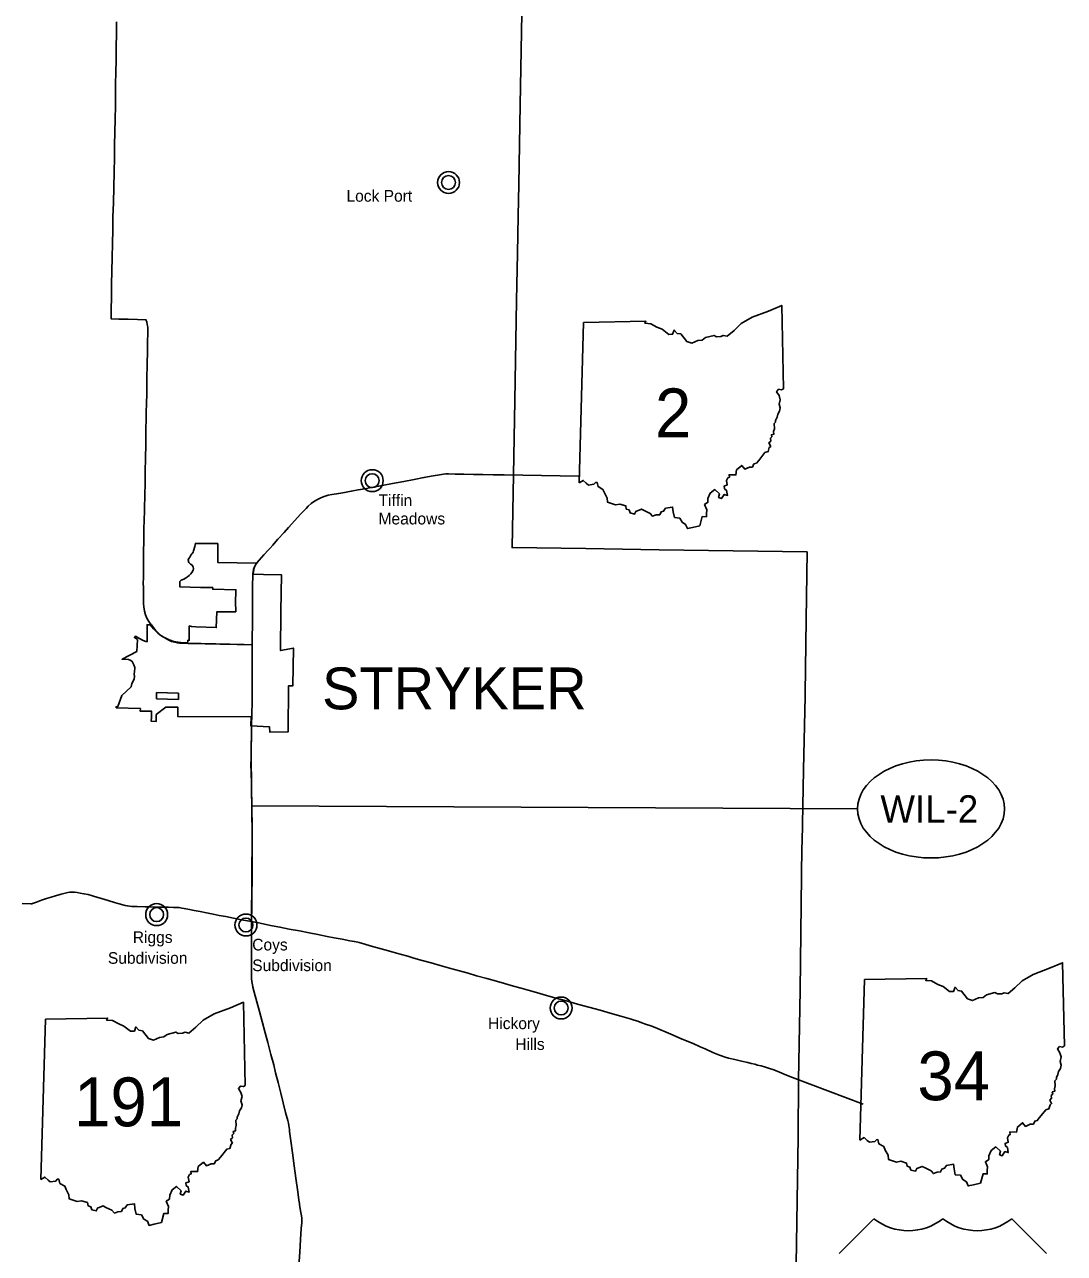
# Model space of a CAD drawing. Extents: x -66 to 795, y 0 to 440.
# Drawn here: x 443.5 to 549.7, y 93.6 to 219 of the extents above; entities that cross this region are included whole.
import ezdxf

# ---------------------------------------------------------------- set-up
doc = ezdxf.new("R2010")
doc.units = 0
for name, color, linetype in [('DV_X_Corp_Line', 7, 'Continuous'), ('GM_X_Corporation_Text', 7, 'Continuous'), ('GM_X_County', 7, 'Continuous'), ('GM_X_State_Route', 7, 'Continuous'), ('PV_P_Text', 7, 'Continuous'), ('RD_P_Fence', 7, 'Continuous'), ('SH_Data', 7, 'Continuous')]:
    doc.layers.add(name, color=color, linetype=linetype)

msp = doc.modelspace()

# ---------------------------------------------------------------- linework, layer by layer
at = {"layer": 'DV_X_Corp_Line'}
for points in [[(452.87, 149.31), (452.87, 149.41), (453.03, 149.42), (453.46, 150.54), (454.41, 151.44), (454.47, 151.77), (454.7, 152.23), (454.73, 152.52), (454.71, 152.71), (454.75, 153.03), (454.78, 153.31), (454.77, 153.42), (454.69, 153.67), (454.51, 154.03), (454.47, 154.07), (454.3, 154.16), (454.12, 154.23), (453.77, 154.26), (453.58, 154.26), (453.47, 154.26), (455, 155.05), (455.06, 156.26), (454.73, 156.47), (454.85, 156.62), (455.18, 156.42), (455.64, 156.15), (455.89, 156.05), (456.03, 156.03), (456.03, 157.77), (456.36, 157.77), (456.55, 157.51), (456.68, 157.36), (456.85, 157.18), (456.98, 157.05), (457.13, 156.92), (457.3, 156.78), (457.45, 156.67), (457.65, 156.55), (457.8, 156.46), (458.2, 156.27), (458.39, 156.19), (458.77, 156.08), (458.98, 156.03), (459.21, 155.99), (459.48, 155.96), (460.16, 155.93), (460.19, 156.07), (460.2, 156.19), (460.34, 156.19), (460.34, 157.65), (460.55, 157.61), (461, 157.57), (463.09, 157.48), (463.14, 159.08), (465.08, 159.1), (465.08, 159.6), (465.07, 159.64), (465.06, 159.93), (465.09, 161.35), (462.73, 161.4), (462.73, 161.57), (461.47, 161.59), (459.38, 161.63), (459.36, 162.18), (459.5, 162.31), (459.79, 162.43), (459.96, 162.53), (460.17, 162.67), (460.31, 162.81), (460.49, 162.97), (460.59, 163.1), (460.73, 163.34), (460.76, 163.51), (460.75, 163.64), (460.74, 163.7), (460.59, 163.89), (460.47, 163.95), (460.37, 164.05), (460.29, 164.13), (460.22, 164.35), (460.25, 164.45), (460.26, 164.52), (460.28, 164.55), (460.38, 164.66), (460.44, 164.75), (460.5, 164.88), (460.6, 165), (460.68, 165.08), (460.73, 165.19), (460.76, 165.32), (460.89, 165.76), (460.96, 166.08), (463.25, 166.05), (463.25, 164.13), (467.19, 164.05), (467.09, 163.88), (466.96, 163.58), (466.89, 163.22), (466.86, 162.93), (467.92, 162.89), (469.74, 162.87), (469.68, 159.11), (469.65, 155.14), (470.96, 155.39), (470.92, 151.54), (470.48, 151.54), (470.42, 146.83), (468.55, 146.82), (468.54, 147.34), (466.63, 147.44), (466.66, 148.37), (459.16, 148.42), (459.17, 148.73), (459.17, 149.36), (457.96, 149.37), (456.97, 148.61), (456.96, 147.9), (456.45, 147.92), (456.47, 148.29), (456.48, 148.96), (455.34, 148.95), (455.35, 149.21)], [(456.99, 150.21), (459.22, 150.15), (459.23, 150.79), (457, 150.85)]]:
    msp.add_lwpolyline(points, close=True, dxfattribs=at)
for centre, radius in [((486.8, 202.91), 1.12), ((486.8, 202.91), 0.71), ((479.01, 172.48), 1.12), ((479.01, 172.48), 0.71), ((457.01, 128.19), 1.12), ((457.01, 128.19), 0.71), ((466.12, 127.13), 1.12), ((466.12, 127.13), 0.71), ((498.29, 118.66), 1.12), ((498.29, 118.66), 0.71)]:
    msp.add_circle(centre, radius, dxfattribs=at)
at = {"layer": 'GM_X_County'}
msp.add_lwpolyline([(522.24, 90.34), (522.47, 105.46), (522.51, 111.32), (522.67, 120.49), (522.87, 135.08), (522.88, 135.57), (523.03, 142.97), (523.18, 150.5), (523.18, 150.8), (523.29, 158.31), (523.39, 165.21), (508.31, 165.43), (500.82, 165.54), (493.28, 165.65), (493.42, 173.06), (493.56, 180.62), (493.75, 190.86), (493.84, 195.67), (493.91, 199.51), (493.97, 202.71), (494.12, 210.82), (494.26, 218.28), (494.39, 225.79)], dxfattribs=at)
at = {"layer": 'GM_X_State_Route'}
for points in [[(452.36, 189.87), (452.36, 190), (452.39, 191.13), (452.41, 192.49), (452.44, 193.89), (452.46, 195.21), (452.5, 196.72), (452.52, 198.03), (452.55, 199.39), (452.59, 200.85), (452.67, 203.99), (452.7, 205.41), (452.72, 206.73), (452.74, 208.05), (452.77, 209.37), (452.79, 210.72), (452.8, 211.88), (452.82, 212.98), (452.84, 214.13), (452.87, 215.39), (452.89, 216.71), (452.9, 218.12), (452.92, 219.3)], [(456.45, 157.78), (456.45, 157.78), (456.21, 158.11), (456.01, 158.46), (455.88, 158.77), (455.78, 159.17), (455.71, 159.59), (455.68, 159.94), (455.66, 160.44), (455.66, 161.24), (455.65, 161.61), (455.64, 161.97), (455.66, 162.59), (455.65, 163.58), (455.66, 164.44), (455.67, 165.34), (455.69, 166.2), (455.69, 166.31), (455.7, 167.37), (455.74, 168.64), (455.75, 169.18), (455.76, 169.69), (455.79, 170.94), (455.83, 172.29), (455.84, 173.41), (455.88, 174.79), (455.9, 176.16), (455.91, 177.72), (455.94, 178.76), (455.95, 179.45), (455.98, 180.4), (455.99, 181.31), (456, 181.51), (456.01, 182.93), (456.04, 184.3), (456.06, 185.77), (456.08, 186.74), (456.11, 187.44), (456.12, 187.85), (456.09, 188.16), (456.05, 188.42), (455.99, 188.68), (455.94, 188.84), (455.92, 188.9), (455.04, 188.93), (454.11, 188.95), (453.13, 188.97), (452.36, 189), (452.36, 189.87), (452.36, 189.87)], [(468.55, 165.56), (468.85, 165.89), (469.01, 166.08), (469.39, 166.5), (470.01, 167.18), (470.48, 167.71), (471.12, 168.42), (471.69, 169.06), (472.25, 169.65), (472.47, 169.89), (472.78, 170.15), (473, 170.31), (473.37, 170.53), (473.68, 170.69), (473.99, 170.84), (474.22, 170.9), (474.51, 170.99), (474.9, 171.05), (475.6, 171.17), (476.17, 171.26), (476.86, 171.39), (477.58, 171.53), (478.27, 171.66), (478.9, 171.78), (478.96, 171.79), (480.02, 171.99), (481.08, 172.2), (482.24, 172.41), (483.29, 172.61), (484.28, 172.79), (485.22, 172.97), (485.88, 173.09), (486.07, 173.12), (486.29, 173.15), (486.51, 173.16), (486.79, 173.16), (487.48, 173.15), (488.37, 173.13), (489.33, 173.12), (489.56, 173.11), (490.31, 173.1), (491.35, 173.09), (492.48, 173.08), (500.09, 172.95)], [(466.82, 162.73), (466.82, 162.8), (466.82, 162.96), (466.85, 163.22), (466.9, 163.42), (466.97, 163.63), (467.09, 163.88), (467.26, 164.12), (467.47, 164.38), (467.93, 164.9), (468.41, 165.41), (468.55, 165.56)], [(466.78, 157.97), (466.78, 158.25), (466.78, 158.5), (466.78, 159.02), (466.79, 159.49), (466.79, 159.57), (466.79, 160.57), (466.79, 161.38), (466.8, 161.98), (466.81, 162.56), (466.82, 162.73), (466.82, 162.73)], [(457.58, 156.61), (457.57, 156.61), (457.45, 156.69), (457.05, 157.04), (456.78, 157.37), (456.48, 157.75), (456.45, 157.78)], [(466.77, 156.63), (466.78, 157.64), (466.78, 157.97)], [(458.08, 156.3), (457.77, 156.47), (457.67, 156.54), (457.58, 156.61)], [(460.23, 155.87), (459.69, 155.88), (459.34, 155.88), (459.13, 155.92), (458.86, 155.98), (458.53, 156.08), (458.19, 156.23), (458.08, 156.3)], [(463.06, 155.81), (463.05, 155.81), (463.04, 155.82), (462.55, 155.83), (461.96, 155.84), (461.56, 155.85), (460.59, 155.87), (460.24, 155.87), (460.23, 155.87)], [(466.77, 155.73), (465.94, 155.76), (465.23, 155.76), (465.21, 155.76), (464.48, 155.78), (464.29, 155.79), (463.46, 155.8), (463.06, 155.81)], [(466.77, 155.73), (466.77, 156.59), (466.77, 156.61), (466.77, 156.62), (466.77, 156.63)], [(466.77, 154.09), (466.77, 154.09), (466.77, 154.85), (466.77, 154.96), (466.77, 155.73)], [(466.77, 151.55), (466.77, 151.55), (466.77, 151.6), (466.77, 151.66), (466.76, 152.26), (466.76, 152.53), (466.76, 153.09), (466.76, 153.23), (466.77, 154.04), (466.77, 154.09)], [(466.71, 148.41), (466.71, 148.41), (466.72, 148.66), (466.72, 148.76), (466.75, 149.85), (466.75, 149.93), (466.76, 150.6), (466.77, 150.9), (466.77, 151.19), (466.77, 151.55)], [(466.7, 147.51), (466.7, 147.52), (466.7, 147.76), (466.71, 148.41)], [(466.7, 127.48), (466.71, 129.07), (466.73, 130.34), (466.74, 131.75), (466.75, 133.12), (466.76, 134.32), (466.77, 135.55), (466.77, 136.31), (466.76, 136.78), (466.74, 137.66), (466.73, 138.61), (466.72, 139.5), (466.7, 140.56), (466.67, 141.56), (466.66, 142.67), (466.63, 143.54), (466.64, 144.08), (466.66, 145.26), (466.7, 146.66), (466.7, 147.51)], [(443.29, 129.31), (444.17, 129.3), (444.28, 129.3), (444.33, 129.31), (444.45, 129.35), (444.75, 129.46), (445.27, 129.66), (445.76, 129.82), (446.23, 129.98), (446.69, 130.11), (447.27, 130.28), (447.67, 130.38), (447.95, 130.44), (448.14, 130.47), (448.38, 130.48), (448.61, 130.47), (448.91, 130.44), (449.2, 130.39), (449.59, 130.32), (450, 130.23), (450.45, 130.11), (451.01, 129.94), (451.63, 129.76), (452.15, 129.6), (452.71, 129.43), (453.19, 129.29), (453.54, 129.2), (453.8, 129.12), (454.02, 129.07), (454.22, 129.05), (454.48, 129.02), (454.72, 129.01), (455.02, 129), (455.83, 128.98), (456.14, 128.97), (456.77, 128.95), (457.56, 128.95), (457.91, 128.95), (458.23, 128.94), (458.74, 128.93), (459.09, 128.91), (459.31, 128.91), (459.56, 128.86), (459.83, 128.81), (460.36, 128.71), (460.85, 128.61), (461.46, 128.49), (462.11, 128.36), (462.79, 128.23), (463.38, 128.11), (464.07, 127.98), (464.84, 127.84), (465.67, 127.67), (466.7, 127.48)], [(471.53, 92.35), (471.63, 93.75), (471.7, 95.03), (471.76, 96.14), (471.81, 96.74), (471.82, 97.04), (471.82, 97.22), (471.79, 97.43), (471.7, 97.96), (471.58, 98.59), (471.57, 98.69), (471.53, 99.05), (471.4, 99.91), (471.22, 101.28), (471.05, 102.54), (470.87, 103.87), (470.7, 105.09), (470.57, 106.06), (470.55, 106.26), (470.5, 106.66), (470.45, 106.9), (470.38, 107.19), (470.16, 108), (469.91, 108.99), (469.67, 109.97), (469.4, 111.04), (469.15, 112.05), (468.96, 112.85), (468.66, 113.91), (468.34, 115.14), (468.08, 116.12), (467.77, 117.27), (467.5, 118.3), (467.24, 119.28), (466.96, 120.28), (466.84, 120.77), (466.79, 121.03), (466.72, 121.35), (466.69, 121.66), (466.67, 122), (466.67, 122.66), (466.67, 123.49), (466.68, 124.39), (466.69, 125.37), (466.7, 127.48)], [(466.7, 127.48), (467.58, 127.31), (468.63, 127.09), (469.59, 126.91), (470.52, 126.72), (471.57, 126.53), (472.56, 126.33), (473.45, 126.16), (474.42, 125.97), (475.14, 125.83), (475.94, 125.68), (476.73, 125.52), (477.19, 125.43), (477.53, 125.37), (477.67, 125.34), (478.27, 125.17), (478.81, 125.01), (479.55, 124.8), (480.31, 124.6), (481.14, 124.36), (481.86, 124.16), (482.63, 123.94), (483.27, 123.76), (484.12, 123.52), (485.04, 123.27), (485.95, 123.01), (486.88, 122.74), (487.91, 122.46), (488.81, 122.21), (489.64, 121.95), (490.69, 121.67)], [(490.69, 121.67), (490.69, 121.67), (491.68, 121.39), (492.51, 121.16), (493.44, 120.9), (494.21, 120.68), (494.92, 120.49), (495.79, 120.24), (496.79, 119.93), (497.02, 119.86), (497.63, 119.69), (498.93, 119.34), (499.97, 119.05), (501.13, 118.73), (502.26, 118.42), (503.28, 118.12), (504.37, 117.82), (505.32, 117.54), (505.75, 117.43), (506.11, 117.3), (506.51, 117.16), (506.9, 117.02), (507.44, 116.83), (507.89, 116.66), (508.36, 116.45), (509, 116.19), (509.74, 115.87), (510.42, 115.58), (511.16, 115.26), (511.75, 115.04), (512.47, 114.71), (512.98, 114.48), (513.77, 114.11), (514.44, 113.84), (514.66, 113.76), (515.03, 113.64), (515.38, 113.53), (516, 113.39), (516.7, 113.22), (517.33, 113.08), (517.69, 113.01), (518.06, 112.91), (518.34, 112.84), (518.72, 112.75), (519.16, 112.62), (519.57, 112.5), (519.88, 112.38), (520.16, 112.28), (520.58, 112.11), (521.3, 111.8), (521.89, 111.56), (529.1, 108.83)]]:
    msp.add_lwpolyline(points, dxfattribs=at)
at = {"layer": 'PV_P_Text'}
for p, q in [((500.12, 172.26), (500.58, 188.63)), ((528.79, 105.18), (529.25, 121.56)), ((528.79, 105.18), (529.25, 121.56)), ((445.19, 101.15), (445.65, 117.52)), ((530.2, 97.15), (526.66, 93.61)), ((530.2, 97.15), (526.66, 93.61)), ((547.84, 93.61), (544.3, 97.15)), ((547.84, 93.61), (544.3, 97.15))]:
    msp.add_line(p, q, dxfattribs=at)
for points in [[(500.58, 188.63), (506.94, 188.74), (506.84, 188.54), (507.44, 188.5), (508.07, 188.15), (508.61, 187.93), (509.27, 187.41), (509.66, 187.42), (509.83, 187.84), (510.13, 187.51), (510.49, 187.45), (511.11, 186.67), (511.62, 186.5), (512.23, 186.77), (512.69, 186.81), (513.03, 187.08), (513.9, 187.31), (514.14, 187.17), (514.6, 187.2), (514.83, 187.3), (515.24, 187.21), (515.95, 187.8), (516.67, 188.51), (517.8, 189.17), (519.47, 189.79), (520.8, 190.36), (520.99, 181.86)], [(520.99, 181.86), (520.79, 181.74), (520.49, 181.8), (520.28, 181.56), (520.54, 181.16), (520.66, 180.74), (520.55, 180.28), (520.66, 179.9), (520.58, 179.58), (520.39, 179.26), (520.33, 178.95), (520.16, 178.63), (520.18, 178.46), (520.02, 178.31), (520.05, 177.78), (519.97, 177.49), (520, 177.23), (519.75, 177.17), (519.81, 176.96), (519.65, 176.8), (519.68, 176.52), (519.5, 176.34), (519.68, 175.98), (519.53, 175.87), (519.42, 175.44), (519.09, 175.35), (518.45, 174.55), (518.22, 174.26), (517.96, 174.18), (517.82, 173.87), (517.51, 173.87), (517.03, 173.66), (516.72, 174.03), (516.18, 173.58), (516.12, 173.07), (515.43, 173.09), (515.46, 172.83), (515.31, 172.76), (515.17, 172.5), (515.25, 172.04), (514.93, 171.92), (514.97, 171.65), (515.17, 171.49), (515.27, 170.98), (514.93, 171.08), (514.65, 170.65), (514.36, 170.75), (514.45, 171.12), (513.97, 171.56), (513.51, 171.21), (513.27, 170.65), (513.27, 170.27), (512.93, 170.04), (513.15, 169.51), (513.11, 169.14), (513.12, 168.79), (512.69, 168.81), (512.43, 167.87)], [(512.43, 167.87), (511.69, 167.69), (511.17, 167.58), (510.99, 168.01), (510.63, 168.23), (510.39, 168.66), (509.86, 168.72), (509.73, 169.31), (509.67, 169.79), (508.95, 169.67), (508.75, 169.38), (508.5, 169.3), (508.35, 169), (508, 168.98), (507.62, 168.84), (507.38, 169.13), (506.76, 169.42), (506.49, 169.57), (505.91, 169.34), (505.79, 169.06), (505.33, 169.18), (505.22, 169.49), (504.94, 169.58), (504.88, 169.91), (504.29, 170.08), (503.83, 170.01), (503.03, 170.28), (502.98, 170.7), (502.71, 171.23), (502.56, 171.59), (502.06, 171.87), (501.95, 172.3), (501.79, 172.29), (501.64, 172.11), (501.08, 172.03), (500.86, 172.21), (500.54, 172.51), (500.12, 172.26)], [(529.25, 121.56), (535.6, 121.66), (535.5, 121.47), (536.1, 121.42), (536.74, 121.07), (537.28, 120.85), (537.94, 120.33), (538.33, 120.34), (538.5, 120.77), (538.8, 120.44), (539.16, 120.38), (539.78, 119.59), (540.29, 119.42), (540.9, 119.69), (541.36, 119.74), (541.69, 120), (542.56, 120.23), (542.81, 120.09), (543.27, 120.12), (543.5, 120.22), (543.9, 120.13), (544.61, 120.73), (545.34, 121.43), (546.46, 122.09), (548.14, 122.72), (549.46, 123.28), (549.66, 114.78)], [(529.25, 121.56), (535.6, 121.66), (535.5, 121.47), (536.1, 121.42), (536.74, 121.07), (537.28, 120.85), (537.94, 120.33), (538.33, 120.34), (538.5, 120.77), (538.8, 120.44), (539.16, 120.38), (539.78, 119.59), (540.29, 119.42), (540.9, 119.69), (541.36, 119.74), (541.69, 120), (542.56, 120.23), (542.81, 120.09), (543.27, 120.12), (543.5, 120.22), (543.9, 120.13), (544.61, 120.73), (545.34, 121.43), (546.46, 122.09), (548.14, 122.72), (549.46, 123.28), (549.66, 114.78)], [(445.65, 117.52), (452, 117.63), (451.9, 117.43), (452.5, 117.39), (453.14, 117.04), (453.67, 116.82), (454.33, 116.3), (454.73, 116.31), (454.89, 116.73), (455.2, 116.4), (455.55, 116.34), (456.17, 115.56), (456.68, 115.39), (457.3, 115.66), (457.75, 115.7), (458.09, 115.97), (458.96, 116.2), (459.2, 116.06), (459.66, 116.09), (459.9, 116.19), (460.3, 116.1), (461.01, 116.69), (461.74, 117.4), (462.86, 118.06), (464.54, 118.69), (465.86, 119.25), (466.05, 110.75)], [(549.66, 114.78), (549.46, 114.66), (549.16, 114.72), (548.95, 114.48), (549.2, 114.08), (549.32, 113.66), (549.22, 113.2), (549.32, 112.82), (549.25, 112.5), (549.06, 112.18), (548.99, 111.88), (548.83, 111.56), (548.84, 111.38), (548.69, 111.24), (548.72, 110.71), (548.64, 110.41), (548.67, 110.16), (548.41, 110.09), (548.47, 109.88), (548.31, 109.72), (548.35, 109.44), (548.17, 109.26), (548.34, 108.91), (548.2, 108.79), (548.08, 108.36), (547.76, 108.27), (547.11, 107.48), (546.89, 107.18), (546.63, 107.1), (546.49, 106.8), (546.17, 106.8), (545.7, 106.58), (545.39, 106.95), (544.85, 106.51), (544.78, 106), (544.1, 106.01), (544.13, 105.75), (543.98, 105.68), (543.84, 105.42), (543.92, 104.96), (543.6, 104.84), (543.64, 104.58), (543.84, 104.41), (543.93, 103.9), (543.59, 104.01), (543.31, 103.58), (543.03, 103.68), (543.12, 104.04), (542.64, 104.48), (542.18, 104.13), (541.94, 103.57), (541.94, 103.19), (541.6, 102.97), (541.81, 102.43), (541.77, 102.07), (541.78, 101.72), (541.36, 101.73), (541.1, 100.79)], [(549.66, 114.78), (549.46, 114.66), (549.16, 114.72), (548.95, 114.48), (549.2, 114.08), (549.32, 113.66), (549.22, 113.2), (549.32, 112.82), (549.25, 112.5), (549.06, 112.18), (548.99, 111.88), (548.83, 111.56), (548.84, 111.38), (548.69, 111.24), (548.72, 110.71), (548.64, 110.41), (548.67, 110.16), (548.41, 110.09), (548.47, 109.88), (548.31, 109.72), (548.35, 109.44), (548.17, 109.26), (548.34, 108.91), (548.2, 108.79), (548.08, 108.36), (547.76, 108.27), (547.11, 107.48), (546.89, 107.18), (546.63, 107.1), (546.49, 106.8), (546.17, 106.8), (545.7, 106.58), (545.39, 106.95), (544.85, 106.51), (544.78, 106), (544.1, 106.01), (544.13, 105.75), (543.98, 105.68), (543.84, 105.42), (543.92, 104.96), (543.6, 104.84), (543.64, 104.58), (543.84, 104.41), (543.93, 103.9), (543.59, 104.01), (543.31, 103.58), (543.03, 103.68), (543.12, 104.04), (542.64, 104.48), (542.18, 104.13), (541.94, 103.57), (541.94, 103.19), (541.6, 102.97), (541.81, 102.43), (541.77, 102.07), (541.78, 101.72), (541.36, 101.73), (541.1, 100.79)], [(466.05, 110.75), (465.86, 110.63), (465.55, 110.69), (465.35, 110.45), (465.6, 110.05), (465.72, 109.63), (465.61, 109.17), (465.72, 108.79), (465.65, 108.47), (465.46, 108.15), (465.39, 107.85), (465.23, 107.53), (465.24, 107.35), (465.09, 107.21), (465.11, 106.67), (465.04, 106.38), (465.06, 106.13), (464.81, 106.06), (464.87, 105.85), (464.71, 105.69), (464.74, 105.41), (464.56, 105.23), (464.74, 104.87), (464.6, 104.76), (464.48, 104.33), (464.16, 104.24), (463.51, 103.45), (463.28, 103.15), (463.03, 103.07), (462.88, 102.76), (462.57, 102.76), (462.09, 102.55), (461.78, 102.92), (461.24, 102.47), (461.18, 101.96), (460.5, 101.98), (460.52, 101.72), (460.37, 101.65), (460.23, 101.39), (460.31, 100.93), (459.99, 100.81), (460.03, 100.54), (460.24, 100.38), (460.33, 99.87), (459.99, 99.97), (459.71, 99.55), (459.42, 99.65), (459.52, 100.01), (459.03, 100.45), (458.58, 100.1), (458.34, 99.54), (458.33, 99.16), (457.99, 98.93), (458.21, 98.4), (458.17, 98.03), (458.18, 97.68), (457.75, 97.7), (457.49, 96.76)], [(541.1, 100.79), (540.36, 100.61), (539.84, 100.5), (539.66, 100.93), (539.29, 101.15), (539.05, 101.58), (538.52, 101.64), (538.4, 102.23), (538.34, 102.71), (537.62, 102.59), (537.42, 102.3), (537.16, 102.22), (537.01, 101.93), (536.66, 101.9), (536.29, 101.76), (536.04, 102.05), (535.43, 102.34), (535.15, 102.49), (534.58, 102.26), (534.45, 101.99), (533.99, 102.11), (533.89, 102.41), (533.61, 102.51), (533.55, 102.83), (532.95, 103.01), (532.5, 102.94), (531.7, 103.2), (531.65, 103.63), (531.37, 104.15), (531.23, 104.52), (530.72, 104.79), (530.62, 105.22), (530.46, 105.21), (530.31, 105.04), (529.75, 104.96), (529.52, 105.13), (529.21, 105.43), (528.79, 105.18)], [(541.1, 100.79), (540.36, 100.61), (539.84, 100.5), (539.66, 100.93), (539.29, 101.15), (539.05, 101.58), (538.52, 101.64), (538.4, 102.23), (538.34, 102.71), (537.62, 102.59), (537.42, 102.3), (537.16, 102.22), (537.01, 101.93), (536.66, 101.9), (536.29, 101.76), (536.04, 102.05), (535.43, 102.34), (535.15, 102.49), (534.58, 102.26), (534.45, 101.99), (533.99, 102.11), (533.89, 102.41), (533.61, 102.51), (533.55, 102.83), (532.95, 103.01), (532.5, 102.94), (531.7, 103.2), (531.65, 103.63), (531.37, 104.15), (531.23, 104.52), (530.72, 104.79), (530.62, 105.22), (530.46, 105.21), (530.31, 105.04), (529.75, 104.96), (529.52, 105.13), (529.21, 105.43), (528.79, 105.18)], [(457.49, 96.76), (456.75, 96.58), (456.24, 96.47), (456.06, 96.9), (455.69, 97.12), (455.45, 97.55), (454.92, 97.61), (454.79, 98.2), (454.74, 98.68), (454.01, 98.56), (453.81, 98.27), (453.56, 98.19), (453.41, 97.89), (453.06, 97.87), (452.69, 97.73), (452.44, 98.02), (451.83, 98.31), (451.55, 98.46), (450.97, 98.23), (450.85, 97.95), (450.39, 98.07), (450.28, 98.38), (450, 98.47), (449.94, 98.8), (449.35, 98.97), (448.89, 98.9), (448.09, 99.17), (448.04, 99.6), (447.77, 100.12), (447.63, 100.48), (447.12, 100.76), (447.02, 101.19), (446.86, 101.18), (446.71, 101), (446.14, 100.92), (445.92, 101.1), (445.6, 101.4), (445.19, 101.15)]]:
    msp.add_lwpolyline(points, dxfattribs=at)
for centre in [(533.73, 101.63), (533.73, 101.63), (540.77, 101.63), (540.77, 101.63)]:
    msp.add_arc(centre, 5.7, 231.813, 308.187, dxfattribs=at)
at = {"layer": 'RD_P_Fence'}
msp.add_lwpolyline([(466.7, 147.51), (466.64, 144.08), (466.77, 136.31), (466.7, 127.48)], dxfattribs=at)
at = {"layer": 'SH_Data'}
msp.add_line((528.54, 138.98), (466.72, 139.28), dxfattribs=at)
msp.add_ellipse((536.04, 138.97), major_axis=(7.5, 0), ratio=0.666667, dxfattribs=at)

# ---------------------------------------------------------------- texts
at = {"layer": 'DV_X_Corp_Line'}
for s, height, p in [('Lock Port', 1.188, (476.38, 200.95)), ('Tiffin', 1.188, (479.65, 169.88)), ('Meadows', 1.188, (479.65, 168.01)), ('Riggs', 1.188, (454.57, 125.29)), ('Coys', 1.188, (466.76, 124.53)), ('Subdivision', 1.1875, (452.03, 123.17)), ('Subdivision', 1.1875, (466.76, 122.42)), ('Hickory', 1.188, (490.83, 116.5)), ('Hills', 1.188, (493.61, 114.38))]:
    msp.add_text(s, height=height, rotation=0, dxfattribs=at).set_placement(p)
at = {"layer": 'GM_X_Corporation_Text'}
msp.add_text('STRYKER', height=4.275, rotation=0, dxfattribs=at).set_placement((473.89, 149.14))
at = {"layer": 'PV_P_Text'}
for s, height, p in [('2', 4.99, (507.87, 176.9)), ('34', 4.987, (534.65, 109.24)), ('191', 4.987, (448.58, 106.58))]:
    msp.add_text(s, height=height, dxfattribs=at).set_placement(p)
at = {"layer": 'SH_Data'}
msp.add_text('WIL-2', height=2.8, dxfattribs=at).set_placement((530.87, 137.57))

doc.saveas('drawing.dxf')
